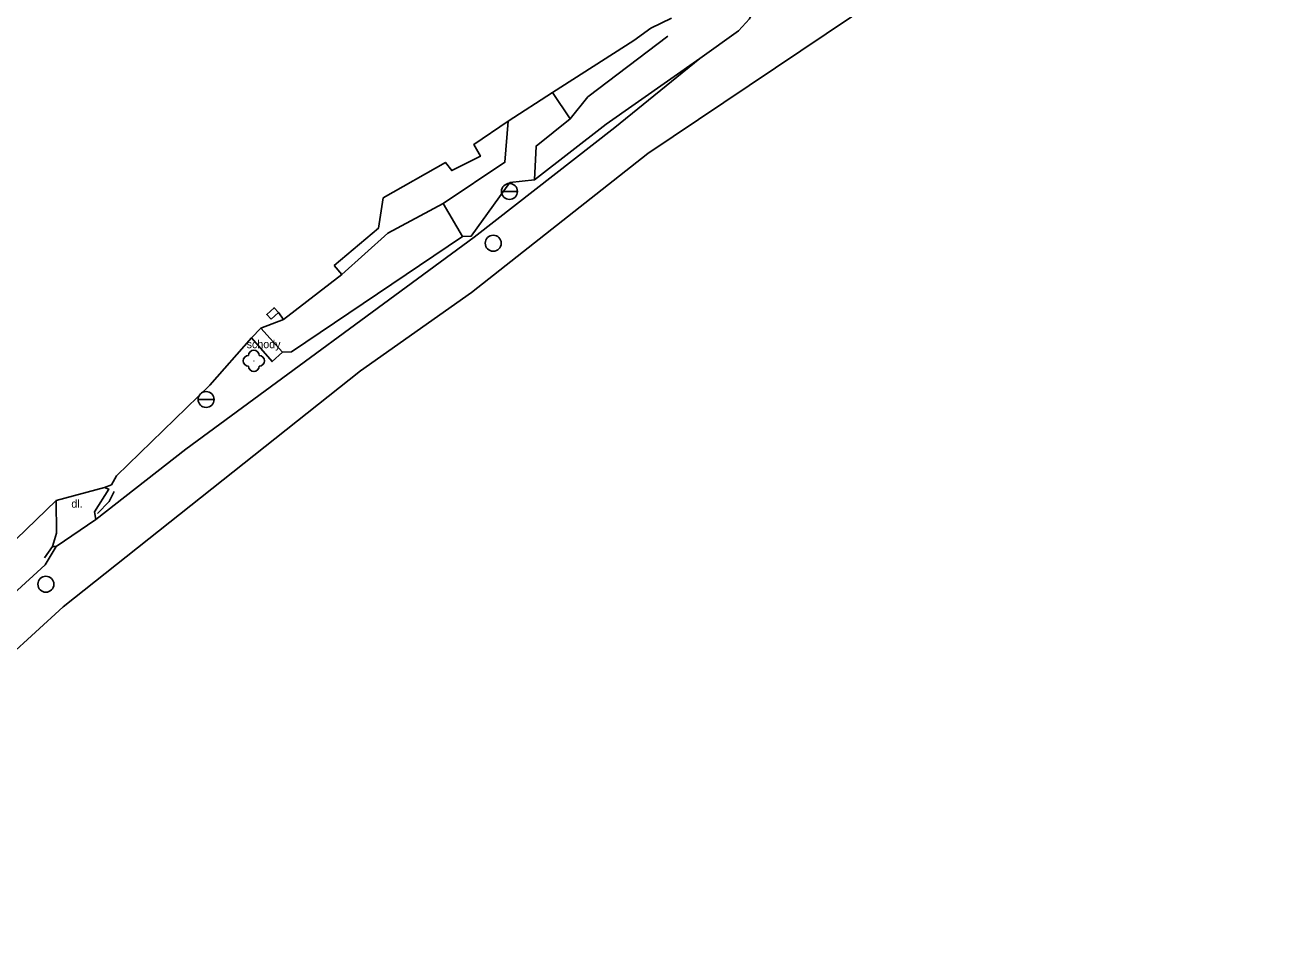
# Model space of a CAD drawing. Extents: x -719449 to -719090, y -950143 to -949819.
# Drawn here: x -719269.6 to -719151.1, y -950061.6 to -949974.5 of the extents above; entities that cross this region are included whole.
import ezdxf

# ---------------------------------------------------------------- set-up
doc = ezdxf.new("R2010")
doc.units = 0
for name, color, linetype in [('Ploty_opěrné zdi', 7, 'Continuous'), ('Popisy objektů_povrchů', 7, 'Continuous'), ('Rozhraní ploch', 7, 'Continuous'), ('Stromy_porost', 7, 'Continuous'), ('Vstup na pozemek', 7, 'Continuous'), ('Výškopis', 7, 'Continuous'), ('Značky IS', 7, 'Continuous')]:
    doc.layers.add(name, color=color, linetype=linetype)

msp = doc.modelspace()

# ---------------------------------------------------------------- linework, layer by layer
at = {"layer": 'Ploty_opěrné zdi'}
for points in [[(-719210.9, -949974.76), (-719208.97, -949973.83)], [(-719212.51, -949975.91), (-719220.12, -949980.81), (-719224.28, -949983.48), (-719227.5, -949985.67), (-719226.88, -949986.77), (-719229.57, -949988.12), (-719230.17, -949987.36), (-719236.01, -949990.68), (-719236.45, -949993.53), (-719240.6, -949997.01)], [(-719240.6, -949997.01), (-719239.89, -949997.87), (-719245.34, -950002.08), (-719245.82, -950001.43)], [(-719262.11, -950017.83), (-719261.47, -950017.59), (-719260.99, -950016.74), (-719252.26, -950008.23), (-719248.34, -950003.81)], [(-719266.66, -950019.04), (-719273.26, -950025.4), (-719275.56, -950022.51)], [(-719266.66, -950019.04), (-719266.62, -950022.12), (-719267, -950023.36), (-719267.76, -950024.42)], [(-719262.77, -950020.27), (-719261.7, -950019.13), (-719261.21, -950018.2)]]:
    msp.add_lwpolyline(points, dxfattribs=at)
at = {"layer": 'Rozhraní ploch'}
for points in [[(-719223.52, -949920.06), (-719222.79, -949919.51), (-719216.39, -949932.89), (-719212.78, -949941.42), (-719210.16, -949946.74), (-719208.22, -949952.3), (-719207.75, -949953.41), (-719203.91, -949959.97), (-719200.35, -949968.43), (-719200.25, -949969.71), (-719200.42, -949970.97), (-719200.85, -949972.16), (-719201.67, -949973.89), (-719202.7, -949975.01), (-719206.32, -949977.62), (-719214.29, -949984.08), (-719227.46, -949994.35), (-719254.49, -950014.24), (-719262.93, -950020.83)], [(-719151.11, -949947.55), (-719151.47, -949946.96), (-719168.26, -949959.32), (-719189.73, -949972.09), (-719211.19, -949986.51), (-719227.72, -949999.55), (-719238.12, -950006.9), (-719265.99, -950029.02), (-719276.4, -950038.53), (-719287.08, -950049.43), (-719285.27, -950051.77)], [(-719248.34, -950003.81), (-719246.41, -950006.02), (-719245.44, -950005.13), (-719247.46, -950002.88)], [(-719262.93, -950020.83), (-719263.06, -950020.12), (-719261.73, -950017.98), (-719262.11, -950017.83)], [(-719262.93, -950020.83), (-719266.64, -950023.37)], [(-719267, -950023.36), (-719266.64, -950023.37), (-719267.67, -950025.07), (-719270.66, -950027.8), (-719285.83, -950042.06), (-719296.81, -950054.28), (-719303.52, -950061.63)]]:
    msp.add_lwpolyline(points, dxfattribs=at)
at = {"layer": 'Stromy_porost'}
msp.add_lwpolyline([(-719220.12, -949980.81), (-719218.48, -949983.28), (-719221.67, -949985.82), (-719221.82, -949988.99), (-719224.12, -949989.23), (-719227.74, -949994.26), (-719228.55, -949994.31), (-719230.37, -949991.22), (-719224.58, -949987.34), (-719224.28, -949983.48)], dxfattribs=at)
msp.add_circle((-719248.12, -950005.96), 0.0005, dxfattribs=at)
for centre, start, end in [((-719248.62, -950005.96), 90, 270), ((-719248.12, -950005.46), 0, 180), ((-719247.62, -950005.96), 270, 90), ((-719248.12, -950006.46), 180, 360)]:
    msp.add_arc(centre, 0.5, start, end, dxfattribs=at)
at = {"layer": 'Vstup na pozemek'}
for points in [[(-719212.51, -949975.91), (-719210.9, -949974.76)], [(-719248.34, -950003.81), (-719247.46, -950002.88)], [(-719266.66, -950019.04), (-719262.11, -950017.83)]]:
    msp.add_lwpolyline(points, dxfattribs=at)
at = {"layer": 'Výškopis'}
for points in [[(-719209.32, -949975.51), (-719216.81, -949981.19), (-719218.48, -949983.28)], [(-719206.32, -949977.62), (-719215.1, -949983.77), (-719221.82, -949988.99)], [(-719230.37, -949991.22), (-719235.56, -949993.99), (-719239.89, -949997.87)], [(-719245.44, -950005.13), (-719244.6, -950005.11), (-719237.89, -950000.58), (-719228.55, -949994.31)], [(-719247.46, -950002.88), (-719245.34, -950002.08)]]:
    msp.add_lwpolyline(points, dxfattribs=at)
at = {"layer": 'Značky IS'}
for p, q in [((-719223.41, -949990.07), (-719224.91, -949990.07)), ((-719251.85, -950009.58), (-719253.35, -950009.58))]:
    msp.add_line(p, q, dxfattribs=at)
msp.add_lwpolyline([(-719246.51, -950002.05), (-719245.82, -950001.43), (-719246.22, -950000.98), (-719246.22, -950000.98), (-719246.91, -950001.6), (-719246.51, -950002.05)], dxfattribs=at)
for centre in [(-719225.68, -949994.93), (-719267.62, -950026.9)]:
    msp.add_circle(centre, 0.75, dxfattribs=at)
for centre, start, end in [((-719224.16, -949990.07), 0, 180), ((-719224.16, -949990.07), 180, 0), ((-719252.6, -950009.58), 0, 180), ((-719252.6, -950009.58), 180, 0)]:
    msp.add_arc(centre, 0.747, start, end, dxfattribs=at)

# ---------------------------------------------------------------- texts
at = {"layer": 'Popisy objektů_povrchů'}
for s, p in [('schody', (-719248.8, -950004.77)), ('dl.', (-719265.23, -950019.72))]:
    msp.add_text(s, height=0.75, dxfattribs=at).set_placement(p)

doc.saveas('drawing.dxf')
